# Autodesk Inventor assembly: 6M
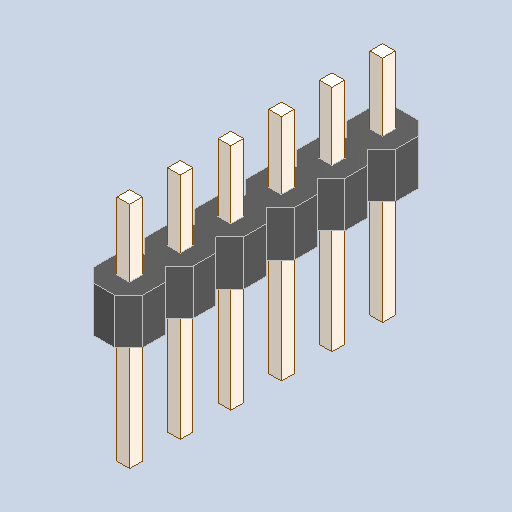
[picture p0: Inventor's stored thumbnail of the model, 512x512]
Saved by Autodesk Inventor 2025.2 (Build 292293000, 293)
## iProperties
Created: 2025-04
Part Number: 6M
Description: PART--DESC
Document SubType Name: Assembly
Designer: BennF
Author: BennF
Revision Number: NONE
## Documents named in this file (3)
- C:\Users\BennF\Nextcloud\Benutzer\CNC JarBeRi\existing parts\Electronics\RepRap A4988 Shied (USE WITHOUT ARDUINO)\reprap-a4988-1.snapshot.1\RepRap\RepRap\6M.iam
- C:\Users\BennF\Nextcloud\Benutzer\CNC JarBeRi\existing parts\Electronics\RepRap A4988 Shied (USE WITHOUT ARDUINO)\reprap-a4988-1.snapshot.1\RepRap\RepRap\6M Geometry.ipt
- C:\Users\BennF\Nextcloud\Benutzer\CNC JarBeRi\existing parts\Electronics\RepRap A4988 Shied (USE WITHOUT ARDUINO)\reprap-a4988-1.snapshot.1\RepRap\RepRap\pin18.ipt
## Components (2 placed, 2 different names)
1. 6M Geometry
2. pin18
